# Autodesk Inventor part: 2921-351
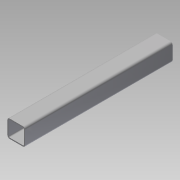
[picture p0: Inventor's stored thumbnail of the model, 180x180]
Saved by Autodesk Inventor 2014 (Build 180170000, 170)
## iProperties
Company: NHTSA/VRTC
Created: 2012-08
Part Number: 2921-351
Material: Steel
Document SubType Name: Modeling
Designer: Mike Vanvoorhis
Density: 7.85 g/cm^3
Mass: 1962.18 g
Surface Area: 1586.12 cm^2
Volume: 249.959 cm^3
Project: CHILD SIDE IMPACT SLED
Description: LOWER ANCHOR BASE TUBE
Stock Number: T.S.2" x 2" x 1/8" x 425.5mm (16.75")
Appearance: Steel
Author: Dave Walker
Title: Lower Anchor Base Tube
Subject: Child Side Impact sled
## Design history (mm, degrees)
sketch "Sketch1"
  geometry: L1 (6.35, 0)-(44.45, 0); L2 (50.8, 6.35)-(50.8, 44.45); L3 (44.45, 50.8)-(6.35, 50.8); L4 (0, 44.45)-(0, 6.35); L5 (6.35, 47.693)-(44.45, 47.693); L6 (47.693, 44.45)-(47.693, 6.35); L7 (44.45, 3.107)-(6.35, 3.107); L8 (3.107, 6.35)-(3.107, 44.45); A1 r 6.35 centre (6.35, 44.45) between (6.35, 50.8) and (0, 44.45); A2 r 6.35 centre (44.45, 44.45) between (50.8, 44.45) and (44.45, 50.8); A3 r 6.35 centre (44.45, 6.35) between (44.45, 0) and (50.8, 6.35); A4 r 6.35 centre (6.35, 6.35) between (0, 6.35) and (6.35, 0); A5 r 3.243 centre (44.45, 44.45) between (47.693, 44.45) and (44.45, 47.693); A6 r 3.243 centre (44.45, 6.35) between (44.45, 3.107) and (47.693, 6.35); A7 r 3.243 centre (6.35, 6.35) between (3.107, 6.35) and (6.35, 3.107); A8 r 3.243 centre (6.35, 44.45) between (6.35, 47.693) and (3.107, 44.45); 4 further points
  constraints: 16 end point, 16 point on circle, 8 centre point, 8 point on line, 8 tangent, 4 parallel, 3 equal radius, 2 perpendicular, 1 horizontal, 7 other
  dimensions: "d0" = 50.8 distance of point (0, 50.8) point (50.8, 50.8); "d1" = 50.8 distance of point (50.8, 50.8) point (50.8, 0); "d2" = 6.35 radius of A1
extrude "Extrusion1" new body sketch "Sketch1" distance "d3" = 425.45; taper "d4" = 0 deg
sketch "Sketch2"
  geometry: L1 (6.35, 47.693)-(44.45, 47.693) reference; L2 (47.693, 44.45)-(47.693, 6.35) reference; L3 (44.45, 3.107)-(6.35, 3.107) reference; L4 (3.107, 6.35)-(3.107, 44.45) reference; L5 (0, 6.35)-(0, 44.45) reference; L6 (44.45, 47.625)-(6.35, 47.625); L7 (3.175, 44.45)-(3.175, 6.35); L8 (6.35, 3.175)-(44.45, 3.175); L9 (47.625, 6.35)-(47.625, 44.45); A1 r 3.243 centre (6.35, 44.45) between (6.35, 47.693) and (3.107, 44.45) reference; A2 r 3.243 centre (44.45, 44.45) between (47.693, 44.45) and (44.45, 47.693) reference; A3 r 3.243 centre (44.45, 6.35) between (44.45, 3.107) and (47.693, 6.35) reference; A4 r 3.243 centre (6.35, 6.35) between (3.107, 6.35) and (6.35, 3.107) reference; A5 r 3.175 centre (6.35, 44.45) between (6.35, 47.625) and (3.175, 44.45); A6 r 3.175 centre (6.35, 6.35) between (3.175, 6.35) and (6.35, 3.175); A7 r 3.175 centre (44.45, 6.35) between (44.45, 3.175) and (47.625, 6.35); A8 r 3.175 centre (44.45, 44.45) between (47.625, 44.45) and (44.45, 47.625); 1 further point
  constraints: 8 end point, 8 point on circle, 4 centre point, 7 other
  dimensions: "d5" = 3.175 distance between parallel lines of L7 L5
extrude "Extrusion2" join sketch "Sketch2" stored distance "d6" = 25.4; taper "d7" = 0 deg
body "Solid1"
